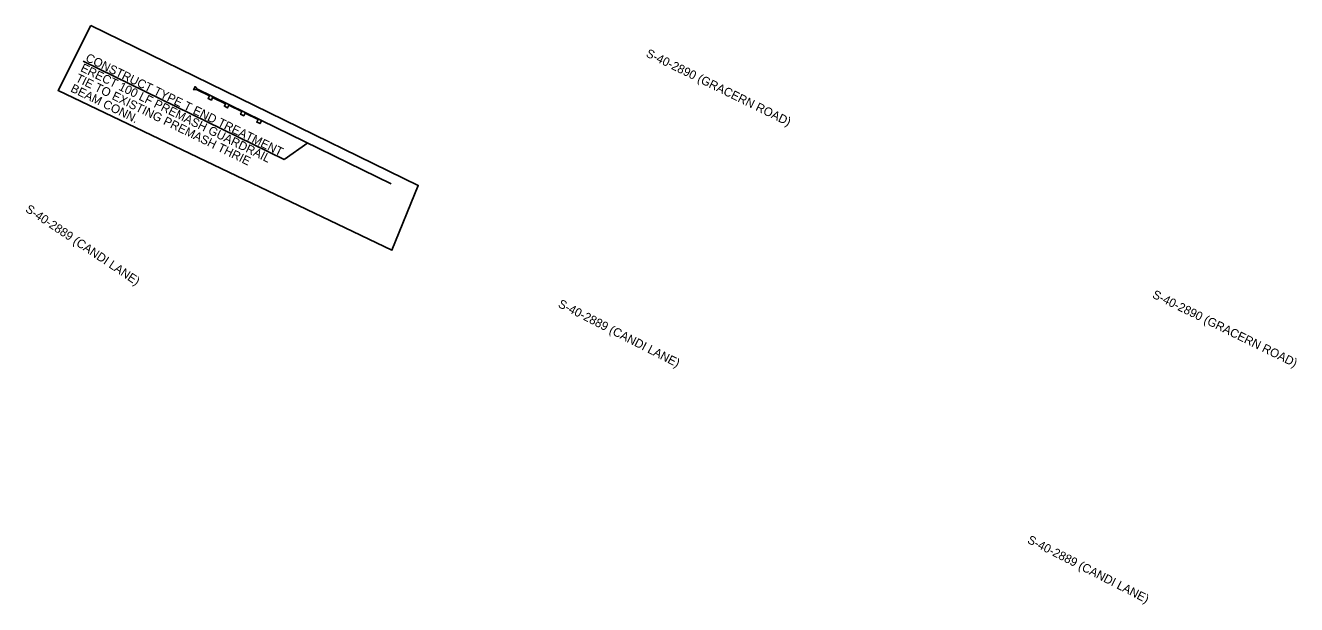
# Model space of a CAD drawing. Extents: x 1966090 to 1975830, y 788086 to 801233.
# Drawn here: x 1974948 to 1975830, y 793142 to 793543 of the extents above; entities that cross this region are included whole.
import ezdxf

# ---------------------------------------------------------------- set-up
doc = ezdxf.new("R2010")
doc.units = 0
for name, color, linetype in [('BR_PRESTRESSED BEAM', 7, 'Continuous'), ('RD_EX_Driveway_txCode', 7, 'Continuous'), ('RD_Sketch6', 7, 'Continuous')]:
    doc.layers.add(name, color=color, linetype=linetype)

msp = doc.modelspace()

# ---------------------------------------------------------------- linework, layer by layer
at = {"layer": 'BR_PRESTRESSED BEAM'}
msp.add_line((1975111.88, 793477.46), (1975201.71, 793433.47), dxfattribs=at)
msp.add_lwpolyline([(1975066.89, 793499.27), (1975111.88, 793477.46), (1975110.79, 793475.21), (1975108.54, 793476.3), (1975109.42, 793478.11), (1975100.42, 793482.47), (1975099.54, 793480.66), (1975097.29, 793481.75), (1975098.17, 793483.56), (1975089.17, 793487.92), (1975088.29, 793486.12), (1975086.04, 793487.21), (1975086.92, 793489.01), (1975077.92, 793493.38), (1975077.05, 793491.57), (1975074.8, 793492.66), (1975075.67, 793494.47), (1975066.67, 793498.83), (1975064.68, 793498.69), (1975065.77, 793500.93)], close=True, dxfattribs=at)
at = {"layer": 'RD_Sketch6'}
for p, q in [((1974988, 793518.61), (1975127.54, 793450.29)), ((1975127.54, 793450.29), (1975143.85, 793461.8))]:
    msp.add_line(p, q, dxfattribs=at)
msp.add_lwpolyline([(1974993.33, 793543.29), (1975220.56, 793432.35), (1975202.25, 793387.46), (1974970.65, 793498.08)], close=True, dxfattribs=at)

# ---------------------------------------------------------------- texts
at = {"layer": 'RD_EX_Driveway_txCode'}
for s, rotation, p in [('S-40-2890 (GRACERN ROAD)', 333.88401, (1975377.96, 793521.97)), ('S-40-2889 (CANDI LANE)', 326.19027, (1974947.53, 793414.6)), ('S-40-2890 (GRACERN ROAD)', 333.88401, (1975729.18, 793354.79)), ('S-40-2889 (CANDI LANE)', 333.00396, (1975317.04, 793348.33)), ('S-40-2889 (CANDI LANE)', 333.00396, (1975642.5, 793184.81))]:
    msp.add_text(s, height=5.9996, rotation=rotation, dxfattribs=at).set_placement(p)
at = {"layer": 'RD_Sketch6'}
for s, height, p in [('CONSTRUCT TYPE T END TREATMENT', 5.9996, (1974989.21, 793518.88)), ('ERECT 100 LF PREMASH GUARDRAIL', 5.9996, (1974985.76, 793511.81)), ('TIE TO EXISTING PREMASH THRIE', 5.9996, (1974982.3, 793504.75)), ('BEAM CONN.', 6, (1974978.85, 793497.68))]:
    msp.add_text(s, height=height, rotation=333.93779, dxfattribs=at).set_placement(p)

doc.saveas('drawing.dxf')
